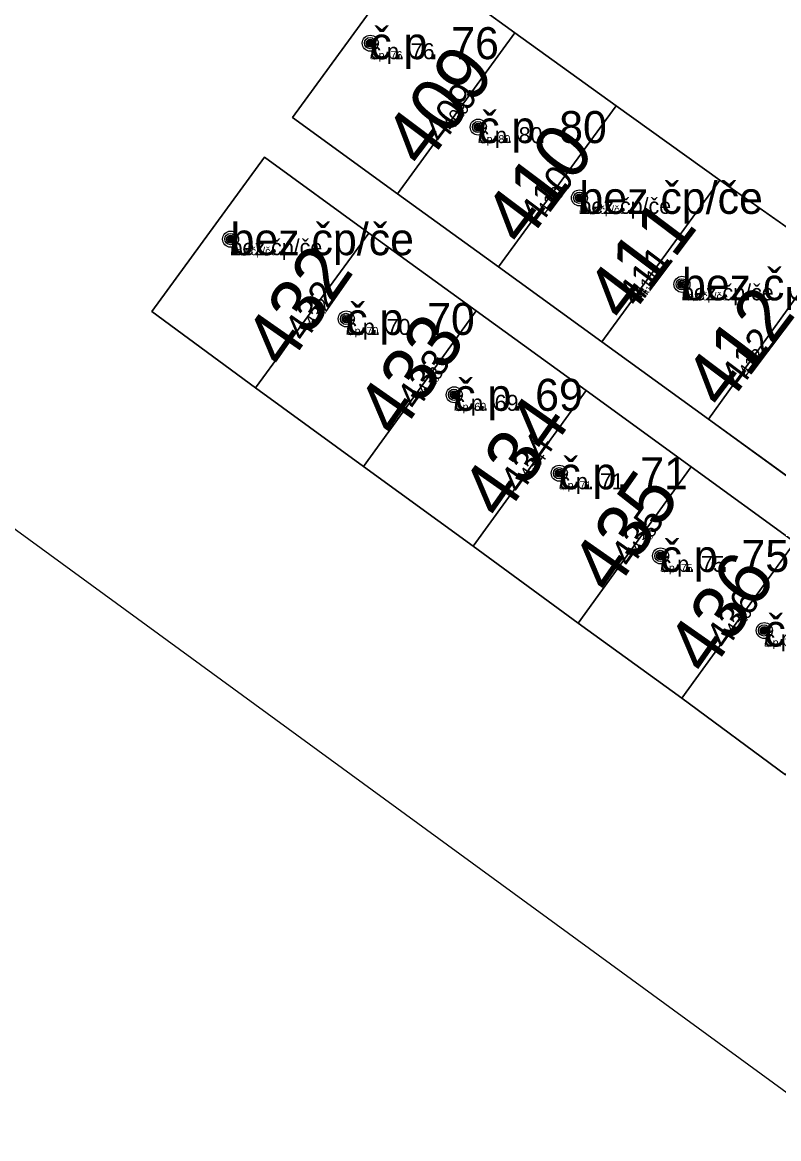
# Model space of a CAD drawing. Extents: x -744652 to -739090, y -980828 to -975855.
# Drawn here: x -742889.54 to -742865.93, y -978620.95 to -978586.09 of the extents above; entities that cross this region are included whole.
import ezdxf

# ---------------------------------------------------------------- set-up
doc = ezdxf.new("R2010")
doc.units = 0
for name, color, linetype in [('KAT_02_hranice parcel', 7, 'Continuous'), ('KAT_03_1000_st čísla parcelní', 7, 'Continuous'), ('KAT_03_1000_čísla popisná', 7, 'Continuous'), ('KAT_03_100_st čísla parcelní', 7, 'Continuous'), ('KAT_03_100_čísla popisná', 7, 'Continuous'), ('KAT_03_250_st čísla parcelní', 7, 'Continuous'), ('KAT_03_250_čísla popisná', 7, 'Continuous'), ('KAT_03_500_st čísla parcelní', 7, 'Continuous'), ('KAT_03_500_čísla popisná', 7, 'Continuous'), ('KAT_07_1000_značky budov', 7, 'Continuous'), ('KAT_07_100_značky budov', 7, 'Continuous'), ('KAT_07_500_značky budov', 7, 'Continuous'), ('KAT_14_plocha_budovy', 7, 'Continuous')]:
    doc.layers.add(name, color=color, linetype=linetype)

msp = doc.modelspace()

# ---------------------------------------------------------------- linework, layer by layer
at = {"layer": 'KAT_02_hranice parcel'}
for p, q in [((-742877.83, -978591.44), (-742874.17, -978586.42)), ((-742874.17, -978586.42), (-742871, -978588.7)), ((-742874.68, -978593.72), (-742871, -978588.7)), ((-742871, -978588.7), (-742867.77, -978591.02)), ((-742871.45, -978596.07), (-742867.77, -978591.02)), ((-742867.77, -978591.02), (-742864.44, -978593.36)), ((-742874.68, -978593.72), (-742877.83, -978591.44)), ((-742882.26, -978597.5), (-742878.72, -978592.67)), ((-742878.72, -978592.67), (-742875.37, -978595.1)), ((-742868.12, -978598.48), (-742864.44, -978593.36)), ((-742871.45, -978596.07), (-742874.68, -978593.72)), ((-742878.89, -978599.96), (-742875.37, -978595.1)), ((-742875.37, -978595.1), (-742871.94, -978597.59)), ((-742868.12, -978598.48), (-742871.45, -978596.07)), ((-742878.89, -978599.96), (-742882.26, -978597.5)), ((-742875.47, -978602.45), (-742871.94, -978597.59)), ((-742871.94, -978597.59), (-742868.66, -978599.97)), ((-742864.89, -978600.83), (-742868.12, -978598.48)), ((-742875.47, -978602.45), (-742878.89, -978599.96)), ((-742872.19, -978604.85), (-742868.66, -978599.97)), ((-742868.66, -978599.97), (-742865.43, -978602.32)), ((-742872.19, -978604.85), (-742875.47, -978602.45)), ((-742868.96, -978607.19), (-742865.43, -978602.32)), ((-742868.96, -978607.19), (-742872.19, -978604.85)), ((-742865.72, -978609.59), (-742868.96, -978607.19))]:
    msp.add_line(p, q, dxfattribs=at)
for points in [[(-742877.83, -978591.44), (-742881.11, -978589.06), (-742877.44, -978584.03), (-742874.17, -978586.42)], [(-742882.26, -978597.5), (-742885.5, -978595.12), (-742881.98, -978590.3), (-742878.72, -978592.67)], [(-742901.1, -978593.64), (-742857.07, -978625.79), (-742852.35, -978619.33)]]:
    msp.add_lwpolyline(points, dxfattribs=at)
at = {"layer": 'KAT_03_1000_čísla popisná'}
for centre in [(-742878.68, -978586.74), (-742878.68, -978586.74), (-742875.31, -978589.36), (-742875.31, -978589.36), (-742872.15, -978591.57), (-742872.15, -978591.57), (-742883.04, -978592.86), (-742883.04, -978592.86), (-742868.95, -978594.27), (-742868.95, -978594.27), (-742879.43, -978595.35), (-742879.43, -978595.35), (-742876.06, -978597.72), (-742876.06, -978597.72), (-742872.78, -978600.17), (-742872.78, -978600.17), (-742869.62, -978602.75), (-742869.62, -978602.75), (-742866.38, -978605.08), (-742866.38, -978605.08)]:
    msp.add_circle(centre, 0.25, dxfattribs=at)
at = {"layer": 'KAT_03_100_čísla popisná'}
for centre in [(-742878.68, -978586.74), (-742878.68, -978586.74), (-742875.31, -978589.36), (-742875.31, -978589.36), (-742872.15, -978591.57), (-742872.15, -978591.57), (-742883.04, -978592.86), (-742883.04, -978592.86), (-742868.95, -978594.27), (-742868.95, -978594.27), (-742879.43, -978595.35), (-742879.43, -978595.35), (-742876.06, -978597.72), (-742876.06, -978597.72), (-742872.78, -978600.17), (-742872.78, -978600.17), (-742869.62, -978602.75), (-742869.62, -978602.75), (-742866.38, -978605.08), (-742866.38, -978605.08)]:
    msp.add_circle(centre, 0.025, dxfattribs=at)
at = {"layer": 'KAT_03_250_čísla popisná'}
for centre in [(-742878.68, -978586.74), (-742878.68, -978586.74), (-742875.31, -978589.36), (-742875.31, -978589.36), (-742872.15, -978591.57), (-742872.15, -978591.57), (-742883.04, -978592.86), (-742883.04, -978592.86), (-742868.95, -978594.27), (-742868.95, -978594.27), (-742879.43, -978595.35), (-742879.43, -978595.35), (-742876.06, -978597.72), (-742876.06, -978597.72), (-742872.78, -978600.17), (-742872.78, -978600.17), (-742869.62, -978602.75), (-742869.62, -978602.75), (-742866.38, -978605.08), (-742866.38, -978605.08)]:
    msp.add_circle(centre, 0.0625, dxfattribs=at)
at = {"layer": 'KAT_03_500_čísla popisná'}
for centre in [(-742878.68, -978586.74), (-742878.68, -978586.74), (-742875.31, -978589.36), (-742875.31, -978589.36), (-742872.15, -978591.57), (-742872.15, -978591.57), (-742883.04, -978592.86), (-742883.04, -978592.86), (-742868.95, -978594.27), (-742868.95, -978594.27), (-742879.43, -978595.35), (-742879.43, -978595.35), (-742876.06, -978597.72), (-742876.06, -978597.72), (-742872.78, -978600.17), (-742872.78, -978600.17), (-742869.62, -978602.75), (-742869.62, -978602.75), (-742866.38, -978605.08), (-742866.38, -978605.08)]:
    msp.add_circle(centre, 0.125, dxfattribs=at)
at = {"layer": 'KAT_07_1000_značky budov'}
for centre in [(-742878.687, -978586.739), (-742875.317, -978589.359), (-742872.157, -978591.569), (-742883.047, -978592.859), (-742868.957, -978594.269), (-742879.437, -978595.349), (-742876.067, -978597.719), (-742872.787, -978600.169), (-742869.627, -978602.749), (-742866.387, -978605.079)]:
    msp.add_circle(centre, 0.175, dxfattribs=at)
at = {"layer": 'KAT_07_100_značky budov'}
for centre in [(-742878.681, -978586.74), (-742875.311, -978589.36), (-742872.151, -978591.57), (-742883.041, -978592.86), (-742868.951, -978594.27), (-742879.431, -978595.35), (-742876.061, -978597.72), (-742872.781, -978600.17), (-742869.621, -978602.75), (-742866.381, -978605.08)]:
    msp.add_circle(centre, 0.0175, dxfattribs=at)
at = {"layer": 'KAT_07_500_značky budov'}
for centre, radius in [((-742878.683, -978586.74), 0.0875), ((-742878.682, -978586.74), 0.0438), ((-742875.313, -978589.36), 0.0875), ((-742875.312, -978589.36), 0.0438), ((-742872.153, -978591.57), 0.0875), ((-742872.152, -978591.57), 0.0438), ((-742883.043, -978592.86), 0.0875), ((-742883.042, -978592.86), 0.0438), ((-742868.953, -978594.27), 0.0875), ((-742868.952, -978594.27), 0.0438), ((-742879.433, -978595.35), 0.0875), ((-742879.432, -978595.35), 0.0438), ((-742876.063, -978597.72), 0.0875), ((-742876.062, -978597.72), 0.0438), ((-742872.783, -978600.17), 0.0875), ((-742872.782, -978600.17), 0.0438), ((-742869.623, -978602.75), 0.0875), ((-742869.622, -978602.75), 0.0438), ((-742866.383, -978605.08), 0.0875), ((-742866.382, -978605.08), 0.0438)]:
    msp.add_circle(centre, radius, dxfattribs=at)
at = {"layer": 'KAT_14_plocha_budovy'}
for points in [[(-742877.44, -978584.03), (-742881.11, -978589.06), (-742877.83, -978591.44), (-742874.17, -978586.42)], [(-742874.17, -978586.42), (-742877.83, -978591.44), (-742874.68, -978593.72), (-742871, -978588.7)], [(-742871, -978588.7), (-742874.68, -978593.72), (-742871.45, -978596.07), (-742867.77, -978591.02)], [(-742881.98, -978590.3), (-742885.5, -978595.12), (-742882.26, -978597.5), (-742878.72, -978592.67)], [(-742867.77, -978591.02), (-742871.45, -978596.07), (-742868.12, -978598.48), (-742864.44, -978593.36)], [(-742878.72, -978592.67), (-742882.26, -978597.5), (-742878.89, -978599.96), (-742875.37, -978595.1)], [(-742864.44, -978593.36), (-742868.12, -978598.48), (-742864.89, -978600.83), (-742861.17, -978595.69)], [(-742871.94, -978597.59), (-742875.37, -978595.1), (-742878.89, -978599.96), (-742875.47, -978602.45)], [(-742871.94, -978597.59), (-742875.47, -978602.45), (-742872.19, -978604.85), (-742868.66, -978599.97)], [(-742868.66, -978599.97), (-742872.19, -978604.85), (-742868.96, -978607.19), (-742865.43, -978602.32)], [(-742865.43, -978602.32), (-742868.96, -978607.19), (-742865.72, -978609.59), (-742862.16, -978604.69)]]:
    msp.add_lwpolyline(points, close=True, dxfattribs=at)

# ---------------------------------------------------------------- texts
at = {"layer": 'KAT_03_1000_st čísla parcelní'}
for s, rotation, p in [('409', 53, (-742877.019, -978590.698)), ('410', 53, (-742873.909, -978593.148)), ('411', 53, (-742870.719, -978595.518)), ('432', 55, (-742881.336, -978596.975)), ('412', 53, (-742867.649, -978598.238)), ('433', 55, (-742877.836, -978599.115)), ('434', 55, (-742874.576, -978601.685)), ('435', 55, (-742871.146, -978604.015)), ('436', 55, (-742868.156, -978606.545))]:
    msp.add_text(s, height=1.7, rotation=rotation, dxfattribs=at).set_placement(p)
at = {"layer": 'KAT_03_1000_čísla popisná'}
for s, p in [('č.p. 76', (-742878.68, -978587.24)), ('č.p. 80', (-742875.31, -978589.86)), ('bez čp/če', (-742872.15, -978592.07)), ('bez čp/če', (-742883.04, -978593.36)), ('bez čp/če', (-742868.95, -978594.77)), ('č.p. 70', (-742879.43, -978595.85)), ('č.p. 69', (-742876.06, -978598.22)), ('č.p. 71', (-742872.78, -978600.67)), ('č.p. 75', (-742869.62, -978603.25)), ('č.p. 72', (-742866.38, -978605.58))]:
    msp.add_text(s, height=1, dxfattribs=at).set_placement(p)
for s, rotation, p in [('409', 53, (-742875.839, -978589.132)), ('410', 53, (-742872.936, -978591.857)), ('411', 53, (-742869.969, -978594.523)), ('432', 55, (-742880.135, -978595.26)), ('412', 53, (-742866.648, -978596.91)), ('433', 55, (-742876.628, -978597.389)), ('434', 55, (-742873.417, -978600.03)), ('435', 55, (-742869.96, -978602.322)), ('436', 55, (-742866.997, -978604.89))]:
    msp.add_text(s, height=0.017, rotation=rotation, dxfattribs=at).set_placement(p)
at = {"layer": 'KAT_03_100_st čísla parcelní'}
for s, rotation, p in [('409', 53, (-742875.946, -978589.274)), ('410', 53, (-742873.025, -978591.974)), ('411', 53, (-742870.038, -978594.614)), ('432', 55, (-742880.244, -978595.416)), ('412', 53, (-742866.739, -978597.031)), ('433', 55, (-742876.737, -978597.546)), ('434', 55, (-742873.522, -978600.18)), ('435', 55, (-742870.068, -978602.476)), ('436', 55, (-742867.102, -978605.04))]:
    msp.add_text(s, height=0.17, rotation=rotation, dxfattribs=at).set_placement(p)
at = {"layer": 'KAT_03_100_čísla popisná'}
for s, p in [('č.p. 76', (-742878.68, -978587.24)), ('č.p. 80', (-742875.31, -978589.86)), ('bez čp/če', (-742872.15, -978592.07)), ('bez čp/če', (-742883.04, -978593.36)), ('bez čp/če', (-742868.95, -978594.77)), ('č.p. 70', (-742879.43, -978595.85)), ('č.p. 69', (-742876.06, -978598.22)), ('č.p. 71', (-742872.78, -978600.67)), ('č.p. 75', (-742869.62, -978603.25)), ('č.p. 72', (-742866.38, -978605.58))]:
    msp.add_text(s, height=0.1, dxfattribs=at).set_placement(p)
for s, rotation, p in [('409', 53, (-742875.828, -978589.118)), ('410', 53, (-742872.927, -978591.845)), ('411', 53, (-742869.963, -978594.514)), ('432', 55, (-742880.124, -978595.244)), ('412', 53, (-742866.639, -978596.898)), ('433', 55, (-742876.617, -978597.373)), ('434', 55, (-742873.406, -978600.015)), ('435', 55, (-742869.95, -978602.306)), ('436', 55, (-742866.986, -978604.875))]:
    msp.add_text(s, height=0.0017, rotation=rotation, dxfattribs=at).set_placement(p)
at = {"layer": 'KAT_03_250_st čísla parcelní'}
for s, rotation, p in [('409', 53, (-742876.125, -978589.512)), ('410', 53, (-742873.172, -978592.17)), ('411', 53, (-742870.151, -978594.764)), ('432', 55, (-742880.426, -978595.676)), ('412', 53, (-742866.891, -978597.232)), ('433', 55, (-742876.92, -978597.808)), ('434', 55, (-742873.698, -978600.431)), ('435', 55, (-742870.248, -978602.732)), ('436', 55, (-742867.278, -978605.291))]:
    msp.add_text(s, height=0.425, rotation=rotation, dxfattribs=at).set_placement(p)
at = {"layer": 'KAT_03_250_čísla popisná'}
for s, p in [('č.p. 76', (-742878.68, -978587.24)), ('č.p. 80', (-742875.31, -978589.86)), ('bez čp/če', (-742872.15, -978592.07)), ('bez čp/če', (-742883.04, -978593.36)), ('bez čp/če', (-742868.95, -978594.77)), ('č.p. 70', (-742879.43, -978595.85)), ('č.p. 69', (-742876.06, -978598.22)), ('č.p. 71', (-742872.78, -978600.67)), ('č.p. 75', (-742869.62, -978603.25)), ('č.p. 72', (-742866.38, -978605.58))]:
    msp.add_text(s, height=0.25, dxfattribs=at).set_placement(p)
for s, rotation, p in [('409', 53, (-742875.83, -978589.12)), ('410', 53, (-742872.929, -978591.847)), ('411', 53, (-742869.964, -978594.516)), ('432', 55, (-742880.126, -978595.247)), ('412', 53, (-742866.641, -978596.9)), ('433', 55, (-742876.618, -978597.376)), ('434', 55, (-742873.408, -978600.017)), ('435', 55, (-742869.951, -978602.309)), ('436', 55, (-742866.988, -978604.877))]:
    msp.add_text(s, height=0.00425, rotation=rotation, dxfattribs=at).set_placement(p)
at = {"layer": 'KAT_03_500_st čísla parcelní'}
for s, rotation, p in [('409', 53, (-742876.423, -978589.907)), ('410', 53, (-742873.418, -978592.496)), ('411', 53, (-742870.34, -978595.016)), ('432', 55, (-742880.729, -978596.109)), ('412', 53, (-742867.144, -978597.567)), ('433', 55, (-742877.226, -978598.243)), ('434', 55, (-742873.991, -978600.849)), ('435', 55, (-742870.547, -978603.16)), ('436', 55, (-742867.571, -978605.709))]:
    msp.add_text(s, height=0.85, rotation=rotation, dxfattribs=at).set_placement(p)
at = {"layer": 'KAT_03_500_čísla popisná'}
for s, p in [('č.p. 76', (-742878.68, -978587.24)), ('č.p. 80', (-742875.31, -978589.86)), ('bez čp/če', (-742872.15, -978592.07)), ('bez čp/če', (-742883.04, -978593.36)), ('bez čp/če', (-742868.95, -978594.77)), ('č.p. 70', (-742879.43, -978595.85)), ('č.p. 69', (-742876.06, -978598.22)), ('č.p. 71', (-742872.78, -978600.67)), ('č.p. 75', (-742869.62, -978603.25)), ('č.p. 72', (-742866.38, -978605.58))]:
    msp.add_text(s, height=0.5, dxfattribs=at).set_placement(p)
for s, rotation, p in [('409', 53, (-742875.833, -978589.124)), ('410', 53, (-742872.931, -978591.85)), ('411', 53, (-742869.966, -978594.518)), ('432', 55, (-742880.129, -978595.251)), ('412', 53, (-742866.643, -978596.903)), ('433', 55, (-742876.621, -978597.38)), ('434', 55, (-742873.411, -978600.021)), ('435', 55, (-742869.954, -978602.313)), ('436', 55, (-742866.991, -978604.881))]:
    msp.add_text(s, height=0.0085, rotation=rotation, dxfattribs=at).set_placement(p)

doc.saveas('drawing.dxf')
